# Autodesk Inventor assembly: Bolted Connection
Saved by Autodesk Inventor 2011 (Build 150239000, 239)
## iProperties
Created: 2020-12
Part Number: Bolted Connection
Document SubType Name: Assembly
Designer: PC
ClientObjectVersion: 1
Author: PC
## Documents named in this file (3)
- C:\Users\PC\Documents\Inventor\workshop-crane-powered-by-drill\estructura-principal\Design Accelerator\Bolted Connection6.iam
- C:\Users\PC\Documents\Inventor\Content Center Files\R2011\en-US\DIN 931-1\DIN 931-1 - M14 x 75.ipt
- C:\Users\PC\Documents\Inventor\Content Center Files\R2011\en-US\DIN 555\DIN 555-5 - M14.ipt
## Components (2 placed, 2 different names)
1. DIN 931-1 - replaced by DIN EN 24014 M14 x 75:1
2. DIN 555 - replaced by DIN EN 24034 M14:1
